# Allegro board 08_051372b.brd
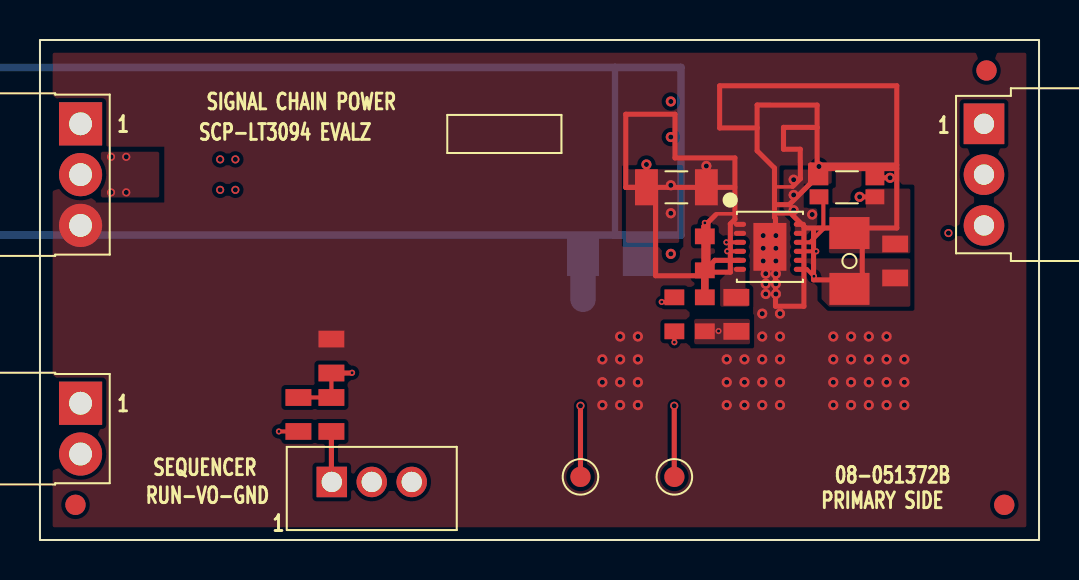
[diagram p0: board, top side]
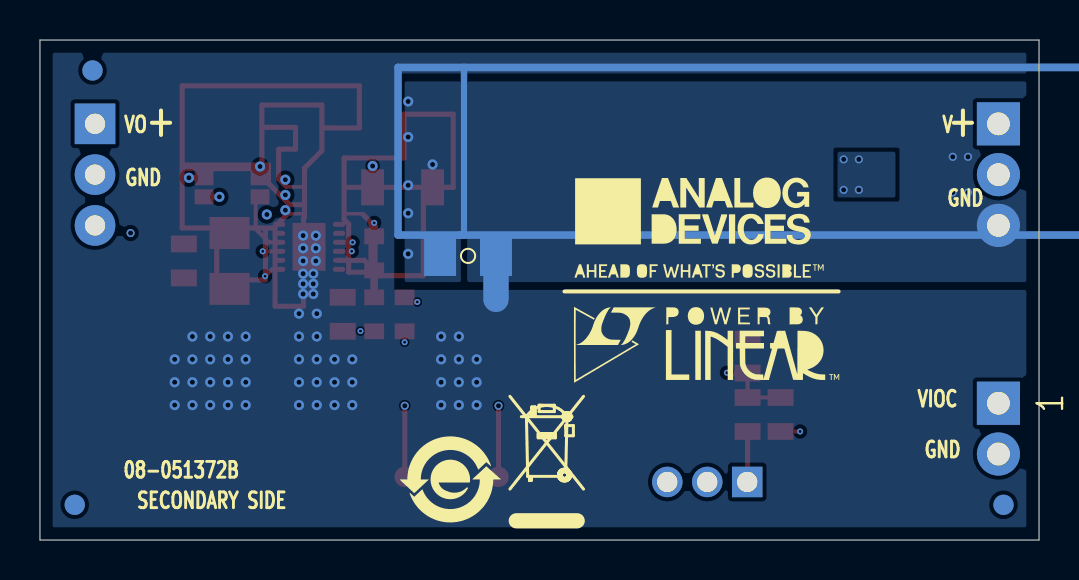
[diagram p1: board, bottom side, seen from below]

Outline 50 x 25 mm; copper layers: TOP, L2_GND, L3_GND, BOTTOM. Coordinates in mm from the lower left corner of the outline.
Outline path: 0,25 50,25 50,0 0,0 0,25

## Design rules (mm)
constraint set DEFAULT: min track width 0.203

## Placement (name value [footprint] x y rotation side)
C1  4.7uF  [C1206H71]  28.57 14.21 0 bottom
C2  10UF  [C1206_SP]  40.39 17.63 0 top
C4  4.7uF  [C1206H71]  40.51 13.95 90 top
C5  TBD1206  [C1206]  31.85 17.63 180 top
INPUT  PBC03SBAN  [CNTHMHDRRA1X3L300W100H145]  2.03 20.81 270 top
NOREF  -  [unnamed]  1.78 1.76 0 top
NOREF#2  -  [#2]  -13.84 237.47 0 top
NOREF#3  -  [#2]  0 25 0 top
NOREF#4  -  [#2]  92.2 43.03 0 top
NOREF#5  -  [#2]  2.03 20.81 0 top
NOREF#6  -  [#2]  -0.02 25.07 270 top
NOREF#7  -  [#2]  0 0 0 top
NOREF#8  -  [#2]  50.02 25.07 180 top
NOREF#9  -  [unnamed]  48.26 1.76 0 top
NOREF#10  -  [#2]  50 0 90 top
NOREF#11  -  [#2]  -36.32 105.77 0 top
NOREF#12  -  [#2]  -69.98 -54.12 0 top
NOREF#13  -  [#2]  50.02 -0.07 90 top
NOREF#14  -  [#2]  25.51 46.03 0 top
NOREF#15  -  [#2]  2.03 20.81 0 top
NOREF#16  -  [unnamed]  47.37 23.48 0 top
NOREF#17  -  [#2]  -0.02 -0.07 0 top
NOREF#18  -  [#2]  0 0 0 top
NOREF#19  -  [#2]  50 0 0 top
NOREF#20  -  [#2]  0 25 0 top
NOREF#21  -  [#2]  -59.69 348.22 0 top
NOREF#22  -  [#2]  24.84 0.64 180 bottom
NOREF#23  -  [unnamed]  1.78 1.76 180 bottom
NOREF#24  -  [unnamed]  48.26 1.76 180 bottom
NOREF#25  -  [#2]  16.64 9.76 180 bottom
NOREF#26  -  [#2]  17.31 15.58 180 bottom
NOREF#27  -  [#2]  29.46 3.03 180 bottom
NOREF#28  -  [unnamed]  47.37 23.48 180 bottom
OUTPUT  PPPC031LGBN-RC  [CNHDRRA1X3H108]  47.24 20.81 270 top
P1  53253-0370  [CNTHMHDR1X3L315W144H224]  14.61 2.9 0 top
PG  TESTPAD  [TPSMC40]  31.75 3.16 0 top
R1  200K  [R0603]  31.75 11.28 90 top
R2  100K  [R0805]  14.59 9.2 270 top
R3  33.2K  [R0805]  42.8 13.95 90 top
R4  TBD0805  [R0805]  12.93 6.28 270 top
R5  453K  [R0603]  33.27 14.33 270 top
R6  49.9K  [R0603]  33.27 11.28 270 top
R7  4.99K  [R0805]  34.85 11.28 270 top
R8  TBD0805  [R0805]  14.59 6.28 90 top
U1  LT3094EDD#PBF  [DFN12_3X3_PAD2_38X1_65]  36.53 14.66 270 top
VEXT  TESTPAD  [TPSMC40]  27.05 3.16 0 top
VIOC  PBC02SBAN  [CNTHMHDRRA1X2L200W100H145]  2.03 6.84 270 top

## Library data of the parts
C1 C4 = CAP: Tolerance: 10; User Part Number: UPN; alternate symbols: (); part number: CAP_SM-4.7UF,25V,10,E018868,C1206H71; tolerance: 10
C2 = CAP_SP: User Part Number: UPN; Tolerance: 10; alternate symbols: (C1206L_SP); part number: CAP_SP_SM-10UF,25V,10,E024739,C1206_SP; tolerance: 10
C5 = CAP: User Part Number: UPN; alternate symbols: (); part number: CAP_SM-TBD1206,TBD1206,TBD1206,E000384,C1206
INPUT = CN3P: Tolerance: N/A; User Part Number: UPN; alternate symbols: (CNTHMHDRRA1X3L300W100H145_SCP); part number: CN3P_TH-PBC03SBAN,E034137,CNTHMHDRRA1X3L300W100H145; tolerance: N/A
OUTPUT = CN3P: User Part Number: UPN; Tolerance: N/A; alternate symbols: (CNHDRRA1X3H108_SCP); part number: CN3P_TH-PPPC031LGBN-RC,E034111,CNHDRRA1X3H108; tolerance: N/A
P1 = CN3P: Tolerance: N/A; User Part Number: UPN; alternate symbols: (); part number: CN3P_TH-53253-0370,E033940,CNTHMHDR1X3L315W144H224; tolerance: N/A
PG VEXT = NCTESTPAD: Tolerance: N/A; User Part Number: UPN; alternate symbols: (); part number: NCTESTPAD_SM-TESTPAD,E019801,TPSMC40; tolerance: N/A
R1 = RES: User Part Number: UPN; Tolerance: 1; alternate symbols: (R0603L); part number: RES_SM-200K,E015343,1/10W,1,R0603; tolerance: 1
R2 = RES: User Part Number: UPN; Tolerance: 1; alternate symbols: (R0805L); part number: RES_SM-100K,E023449,1/3W,1,R0805; tolerance: 1
R3 = RES: User Part Number: UPN; Tolerance: 1; alternate symbols: (R0805L); part number: RES_SM-33.2K,E003645,1/8W,1,R0805; tolerance: 1
R4 R8 = RES: User Part Number: UPN; alternate symbols: (R0805L); part number: RES_SM-TBD0805,E004051,TBD0805,TBD0805,R0805
R5 = RES: User Part Number: UPN; Tolerance: 1; alternate symbols: (); part number: RES_SM-453K,E032192,1/10W,1,R0603; tolerance: 1
R6 = RES: User Part Number: UPN; Tolerance: 1; alternate symbols: (R0603L); part number: RES_SM-49.9K,E015342,1/10W,1,R0603; tolerance: 1
R7 = RES: User Part Number: UPN; Tolerance: 1; alternate symbols: (R0805L); part number: RES_SM-4.99K,E003493,1/8W,1,R0805; tolerance: 1
U1 = LINLT3094: User Part Number: UPN; Tolerance: N/A; alternate symbols: (); part number: LINLT3094_SM-LT3094EDD#PBF,E033630,DFN12_3X3_PAD2_38X1_65; tolerance: N/A
VIOC = CN2P: Tolerance: N/A; User Part Number: UPN; alternate symbols: (CNTHMHDRRA1X2L200W100H145_SCP); part number: CN2P_TH-PBC02SBAN,E034136,CNTHMHDRRA1X2L200W100H145; tolerance: N/A

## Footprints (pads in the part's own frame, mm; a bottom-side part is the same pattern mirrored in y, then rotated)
C1206
  rect 1.143x1.803 smd: 1(-1.5,0) 2(1.5,0)
C1206_SP
  rect 0.94x0.749 smd: 1(-1.4,-0.476) 2(1.4,-0.476) 3(1.4,0.476) 4(-1.4,0.476)
C1206H71
  rect 1.6x2.007 smd: 1(-1.397,0) 2(1.397,0)
CNHDRRA1X3H108
  rect 2.032x2.032 hole 1.016: 1(0,0)
  round 2.032 hole 1.016: 2(2.54,0) 3(5.08,0)
CNTHMHDR1X3L315W144H224
  rect 1.524x1.524 hole 1.016: 1(0,0)
  round 1.524 hole 1.016: 2(2,0) 3(4,0)
CNTHMHDRRA1X2L200W100H145
  rect 2.159x2.159 hole 1.143: 1(0,0)
  round 2.159 hole 1.143: 2(2.54,0)
CNTHMHDRRA1X3L300W100H145
  rect 2.159x2.159 hole 1.143: 1(0,0)
  round 2.159 hole 1.143: 2(2.54,0) 3(5.08,0)
DFN12_3X3_PAD2_38X1_65
  oval 0.254x0.61 smd: 1(-1.125,-1.5) 2(-0.675,-1.5) 3(-0.225,-1.5) 4(0.225,-1.5) 5(0.675,-1.5) 6(1.125,-1.5) 7(1.125,1.5) 8(0.675,1.5) 9(0.225,1.5) 10(-0.225,1.5) 11(-0.675,1.5) 12(-1.125,1.5)
  rect 2.388x1.651 smd: PAD(0,0)
R0603
  rect 0.787x0.991 smd: 1(-0.85,0) 2(0.85,0)
R0805
  rect 0.838x1.295 smd: 1(-0.85,0) 2(0.85,0)
TPSMC40
  round 1.016 smd: 1(0,0)
unnamed
  round 1.016 smd: (0,0)

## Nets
GND: C1.2(N2) C2.2 C2.3 C4.2(N2) C5.2(N2) INPUT.2 OUTPUT.2 P1.3(N3) R3.2(N2) R4.2(N2) R6.2(N2) R7.2(N2) U1.9 VIOC.2(N2)
RUN: P1.1 R8.1
UNNAMED_2_CAP_I4_N1: C4.1 R3.1 U1.8
UNNAMED_2_CAP_I14_N1: C1.1 C5.1 INPUT.3(N3) R2.1 U1.1 U1.2 U1.PAD
UNNAMED_2_CAPSP_I5_N1: C2.1 U1.10
UNNAMED_2_LINLT3094_I2_EN: R2.2(N2) R4.1 R8.2(N2) U1.3
UNNAMED_2_LINLT3094_I2_ILIM: R7.1 U1.6
UNNAMED_2_LINLT3094_I2_PG: PG.1(N1) R1.1 U1.4
UNNAMED_2_LINLT3094_I2_PGFB: R5.2(N2) R6.1 U1.5
UNNAMED_2_NCTESTPAD_I16_N1: R1.2(N2) VEXT.1(N1)
VIOC: U1.7(VIOC) VIOC.1
VO-: C2.4(N4) OUTPUT.3(N3) P1.2 R5.1 U1.11 U1.12

Pads without a net: INPUT 1; OUTPUT 1

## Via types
v1: diameter 0.305, hole 0.152, TOP to BOTTOM, 10 vias
v2: diameter 0.508, hole 0.254, TOP to BOTTOM, 72 vias
v3: diameter 0.406, hole 0.254, TOP to BOTTOM, 11 vias

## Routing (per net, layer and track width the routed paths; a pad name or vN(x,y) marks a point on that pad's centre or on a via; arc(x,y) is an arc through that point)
GND: length 4.5
  TOP w0.203: R4.2 v1(11.96,5.43) ; v1(38.85,14.43) U1.9 ; C5.2 v2(30.35,18.78)
  TOP w0.254: C2.2 v2(41.02,17.16) ; C2.3 v2(42.55,18.11)
  vias: v1(33.96,10.45) v2(31.57,21.93) v2(31.57,20.15) v2(31.57,17.74) v2(31.57,16.34) v2(31.57,14.31) v3(9.02,19.03) v3(9.02,17.51) v3(9.78,19.03) v3(9.78,17.51)
RUN: length 2.5
  TOP w0.254: P1.1 14.59,2.92 R8.1
UNNAMED_2_CAP_I14_N1: length 2.2
  BOTTOM w1.27: 27.18,12.03 C1.1 27.18,14.24
  vias: v2(28.15,9.03) v2(28.15,7.89) v2(28.15,6.75) v2(29.04,10.17) v2(29.04,9.03) v2(29.04,7.89) v2(29.04,6.75) v2(29.92,10.17) v2(29.92,9.03) v2(29.92,7.89) v2(29.92,6.75) v2(33.35,18.7) v2(34.37,9.03) v2(34.37,7.89) v2(34.37,6.75) v2(35.26,9.03) v2(35.26,7.89) v2(35.26,6.75) v2(36.15,11.32) v2(36.15,10.17) v2(36.15,9.03) v2(36.15,7.89) v2(36.15,6.75) v2(36.19,15.22) v2(36.19,14.59) v2(36.19,13.95) v2(36.32,13.32) v2(36.32,12.81) v2(36.32,12.3) v2(36.83,15.22) v2(36.83,14.59) v2(36.83,13.95) v2(36.83,13.32) v2(36.83,12.81) v2(36.83,12.3) v2(37.04,11.32) v2(37.04,10.17) v2(37.04,9.03) v2(37.04,7.89) v2(37.04,6.75) v2(39.7,10.17) v2(39.7,9.03) v2(39.7,7.89) v2(39.7,6.75) v2(40.59,10.17) v2(40.59,9.03) v2(40.59,7.89) v2(40.59,6.75) v2(41.48,10.17) v2(41.48,9.03) v2(41.48,7.89) v2(41.48,6.75) v2(42.37,10.17) v2(42.37,9.03) v2(42.37,7.89) v2(42.37,6.75) v2(43.26,9.03) v2(43.26,7.89) v2(43.26,6.75) v3(3.56,19.16) v3(3.56,17.38) v3(4.32,19.16) v3(4.32,17.38)
UNNAMED_2_CAPSP_I5_N1: length 3.1
  TOP w0.203: C2.1 39.2,16.94 39.2,15.55 38.53,14.88 U1.10
UNNAMED_2_LINLT3094_I2_EN: length 26
  TOP w0.203: R2.2 R8.2 R4.1 ; v1(34.35,14.88) U1.3
  TOP w0.254: v1(15.62,8.36) 15.61,8.35 R2.2
  L2_GND w0.254: v1(15.62,8.36) 17.4,8.36 22.05,13.01 31.11,13.01 32.99,14.88 v1(34.35,14.88)
UNNAMED_2_LINLT3094_I2_PG: length 13.6
  TOP w0.203: U1.4 34.42,14.43 34.42,14.44 v1(34.4,14.44) ; R1.1 v1(31.75,9.89)
  TOP w0.254: PG.1 31.74,3.16 v3(31.74,6.71)
  L2_GND w0.254: v3(31.74,6.71) 31.74,9.88 v1(31.75,9.89) 34.4,12.53 v1(34.4,14.44)
UNNAMED_2_LINLT3094_I2_PGFB: length 3.3
  TOP w0.254: U1.5 33.78,13.98 R5.2
  TOP w0.381: R6.1 R5.2
UNNAMED_2_NCTESTPAD_I16_N1: length 12.2
  TOP w0.203: R1.2 31.52,11.9 v1(31.11,11.9)
  TOP w0.254: v3(27.05,6.71) VEXT.1
  L2_GND w0.254: v1(31.11,11.9) 30.5,11.28 28.7,11.28 27.05,9.63 v3(27.05,6.71)
VIOC: length 45.1
  TOP w0.203: v1(38.73,13.19) 38.39,13.53 U1.7
  L3_GND w0.254: v1(38.73,13.19) 38.73,6.6 37.71,5.57 20.07,5.57 18.8,6.84 VIOC.1
VO-: length 46.7
  TOP w0.254: R5.1 v1(33.27,15.86) ; C2.4 v2(38.99,18.68)
  L2_GND w0.381: v3(45.47,15.35) 45.47,6.33 40.64,1.51 18,1.51 P1.2
  L3_GND w0.254: 38,16.54 38,16.54 33.96,16.54 v1(33.27,15.86)
  vias: v2(37.72,18.02) v2(37.72,17.25) v2(37.72,16.49) v2(38.65,16.28)

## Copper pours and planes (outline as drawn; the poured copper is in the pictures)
GND on TOP: 29.32,14.85 29.32,18.54 31.99,18.54 31.99,14.85
GND on TOP: 32.74,11.06 32.74,9.79 35.53,9.79 35.53,11.06
GND on TOP: 39.48,14.33 39.48,16.62 41.34,16.62 41.34,17.57 43.56,17.57 43.56,14.33
GND on BOTTOM: 28.94,12.9 28.94,22.93 31.75,22.93 31.75,12.9
GND on BOTTOM: 7.19,19.41 7.19,17.13 10.08,17.13 10.08,19.41
GND on L2_GND: 0.64,0.64 0.64,24.36 4.95,24.36 6.1,24.37 8.13,24.36 10.29,24.37 49.36,24.36 49.36,0.64 ; 8 cut-outs
GND on L3_GND: 0.64,0.64 0.64,12.81 32,12.81 32,23.1 0.64,23.1 0.64,24.36 49.36,24.36 49.36,0.64 ; 1 cut-out
GND on L3_GND: 0.64,22.93 0.64,12.9 31.89,12.9 31.89,22.93 ; 1 cut-out
UNNAMED_2_CAP_I4_N1 on TOP: 39.5,11.67 43.56,11.67 43.56,14.08 37.85,14.08 37.85,13.82 38.48,13.82 39.12,13.19 39.12,12.05
UNNAMED_2_CAP_I14_N1 on TOP: 0.64,0.64 0.64,12.55 0.64,12.68 0.64,14.84 0.64,21.32 0.64,23.35 0.64,24.36 49.36,24.36 49.36,0.64 ; 3 cut-outs
UNNAMED_2_CAP_I14_N1 on TOP: 3.05,19.41 3.05,17.13 5.97,17.13 5.97,19.41
UNNAMED_2_CAP_I14_N1 on BOTTOM: 0.64,12.9 0.64,22.93 28.62,22.93 28.62,12.9
UNNAMED_2_CAP_I14_N1 on BOTTOM: 0.64,0.64 0.64,12.5 32.27,12.5 32.27,23.32 0.64,23.32 0.64,24.36 49.36,24.36 49.36,0.64 ; 1 cut-out
UNNAMED_2_LINLT3094_I2_ILIM on TOP: 34.04,11.67 34.04,13 34.7,13.67 34.7,13.65 35.31,13.65 35.31,12.61 35.36,12.61 35.48,12.48 35.48,11.67
VO- on TOP: 37.78,15.22 37.78,15.98 37.21,16.55 37.21,18.52 39.62,18.52 39.62,17.81 38.23,17.81 38.23,16.62 38.94,16.62 38.94,15.83 38.34,15.22
VO- on L3_GND: 38.51,14.84 37.24,16.11 37.24,19.39 49.36,19.39 49.36,14.84 ; 1 cut-out

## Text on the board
Ref Des/Silkscreen Bottom: GND | V | VIOC | SECONDARY SIDE | 08-051372B | VO | +
Ref Des/Silkscreen Top: SEQUENCER | RUN-VO-GND | SCP-LT3094 EVALZ | SIGNAL CHAIN POWER | PRIMARY SIDE | 08-051372B
PAGE_OUTLINE: N/A | 18DEC18 | B | AS PER ECR-086562 | 07MAY19 | J.VIERNES
DIMENSION: (REF) | SEE FAB NOTE 15 | DIA MAX
User.11: 4.    RoHS COMPLIANCE: ASSEMBLY VENDOR SHOULD ASSURE COMPLIANCE | VIEW FROM PRIMARY SIDE | WITH LEAD-FREE AND RoHS PCB ASSEMBLY STANDARDS (EU RoHS | DIRECTIVE 2002/95/EC). | VIEW FROM SECONDARY SIDE
User.15: 15.    THRU VIAS TO BE FILLED WITH SOLDERMASK. | .0028" | .0014" | .0035"
User.17: L2 GND | 08-      -07
User.18: L3 GND | 08-      -08
User.45: FIGURE | SIZE | 6.0 | 10.0 | 40.0 | 45.0 | PLATED | FINISHED HOLES IN MILS | ALL UNITS ARE IN MILS | QTY | 10 | 83 | 6 | 5 | TOLERANCE/NOTES
